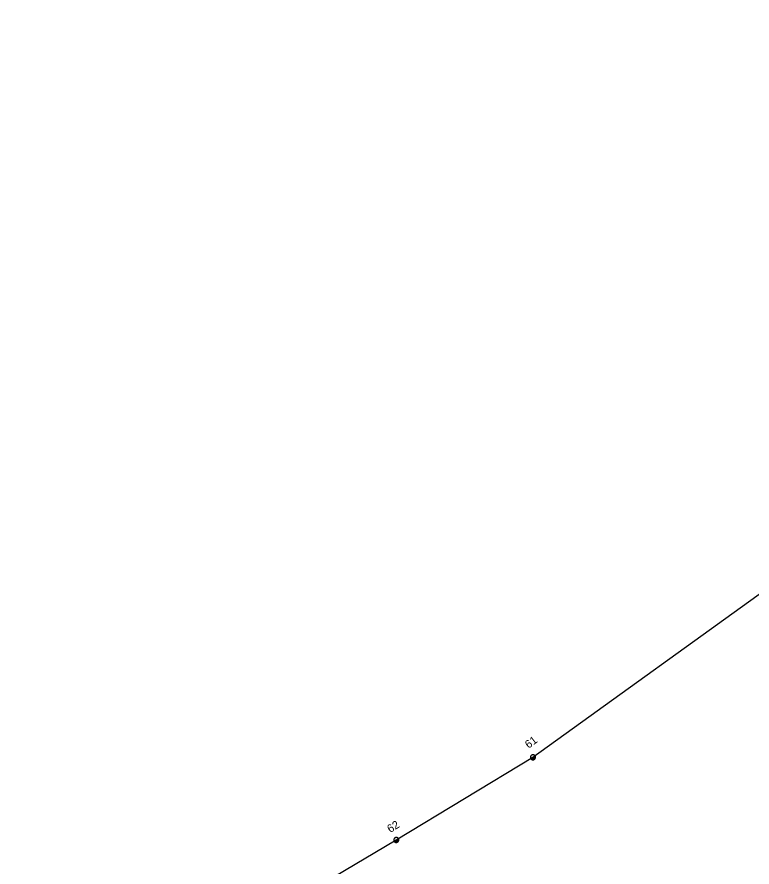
# Model space of a CAD drawing. Extents: x -544780 to -541582, y -1198995 to -1196551.
# Drawn here: x -542924.7 to -542832.9, y -1198121 to -1198014.8 of the extents above; entities that cross this region are included whole.
import ezdxf

# ---------------------------------------------------------------- set-up
doc = ezdxf.new("R2010")
doc.units = 0
for name, color, linetype in [('Vrstva 1', 7, 'Continuous'), ('Vrstva 13', 7, 'Continuous'), ('Vrstva 14', 7, 'Continuous'), ('Vrstva 2', 7, 'Continuous')]:
    doc.layers.add(name, color=color, linetype=linetype)

# ---------------------------------------------------------------- blocks, each defined once
blk = doc.blocks.new('NN440')
at = {"layer": 'Vrstva 2'}
for points in [[(0.63, 0), (0.63, 0.06), (0.62, 0.13), (0.6, 0.19), (0.58, 0.25), (0.55, 0.31), (0.51, 0.37), (0.47, 0.42), (0.42, 0.46), (0.37, 0.51), (0.32, 0.54), (0.26, 0.57), (0.2, 0.59), (0.13, 0.61), (0.07, 0.62), (0, 0.63), (-0.06, 0.62), (-0.13, 0.61), (-0.19, 0.59), (-0.26, 0.57), (-0.31, 0.54), (-0.37, 0.51), (-0.42, 0.46), (-0.47, 0.42), (-0.51, 0.37), (-0.54, 0.31), (-0.57, 0.25), (-0.6, 0.19), (-0.62, 0.13), (-0.63, 0.06), (-0.63, 0), (-0.63, -0.07), (-0.62, -0.14), (-0.6, -0.2), (-0.57, -0.26), (-0.54, -0.32), (-0.51, -0.37), (-0.47, -0.43), (-0.42, -0.47), (-0.37, -0.51), (-0.31, -0.55), (-0.26, -0.58), (-0.19, -0.6), (-0.13, -0.62), (-0.06, -0.63), (0, -0.63), (0.07, -0.63), (0.13, -0.62), (0.2, -0.6), (0.26, -0.58), (0.32, -0.55), (0.37, -0.51), (0.42, -0.47), (0.47, -0.43), (0.51, -0.37), (0.55, -0.32), (0.58, -0.26), (0.6, -0.2), (0.62, -0.14), (0.63, -0.07), (0.63, 0)], [(-0.63, 0), (0.63, 0)], [(-0.6, -0.18), (0.57, -0.18)], [(-0.51, -0.32), (0.5, -0.32)], [(-0.37, -0.47), (0.35, -0.47)]]:
    blk.add_lwpolyline(points, dxfattribs=at)

msp = doc.modelspace()

# ---------------------------------------------------------------- linework, layer by layer
at = {"layer": 'Vrstva 1'}
msp.add_lwpolyline([(-542924.66, -1198163.13), (-542924.66, -1198163.13), (-542909.26, -1198142.87), (-542899.34, -1198130.66), (-542877.32, -1198117.58), (-542860.26, -1198107.27), (-542829.18, -1198084.86), (-542796.92, -1198061.21), (-542778.91, -1198047.94), (-542757.02, -1198030.94), (-542736.62, -1198014.82)], dxfattribs=at)

# ---------------------------------------------------------------- block references
at = {"layer": 'Vrstva 13', "xscale": 0.5, "yscale": 0.5}
for p, rotation in [((-542860.26, -1198107.27), 36.94052218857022), ((-542877.32, -1198117.59), 32.43960563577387)]:
    msp.add_blockref('NN440', p, dxfattribs=dict(at, rotation=rotation))

# ---------------------------------------------------------------- texts
at = {"layer": 'Vrstva 14'}
for s, rotation, p in [('61', 36.941, (-542860.8, -1198106.22)), ('62', 32.44, (-542878.07, -1198116.74))]:
    msp.add_text(s, height=1, rotation=rotation, dxfattribs=at).set_placement(p)

doc.saveas('drawing.dxf')
